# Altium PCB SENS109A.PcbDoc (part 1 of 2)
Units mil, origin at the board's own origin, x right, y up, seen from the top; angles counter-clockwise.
Board outline 2760 x 2518.85 mil, 4 copper layers (Top Layer, Signal Layer 1, Signal Layer 2, Bottom Layer), stack 62.2 mil thick; 49 components, 21 nets, 113 pads, 294 vias.
Unrouted connection lines stored in the file: 4.
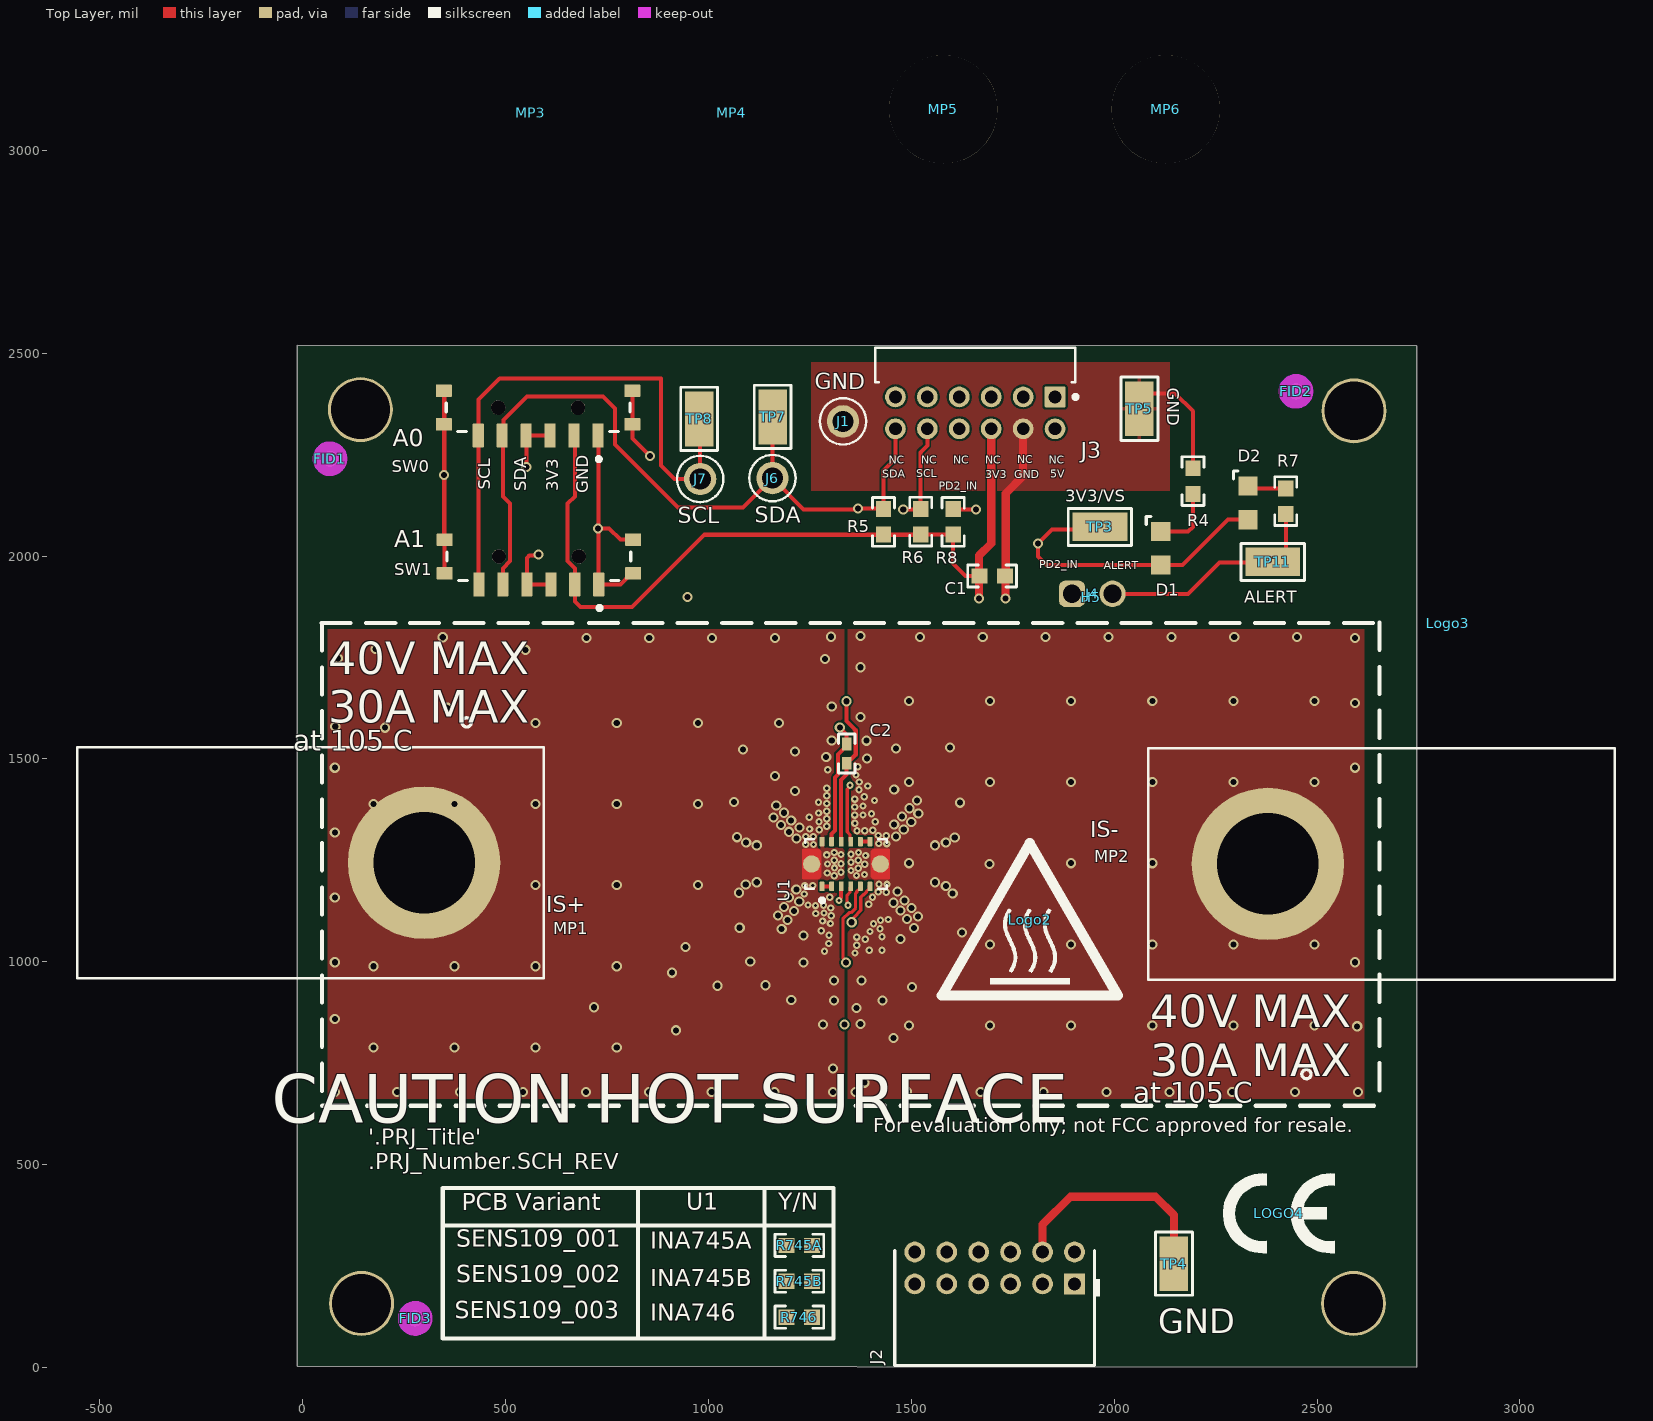
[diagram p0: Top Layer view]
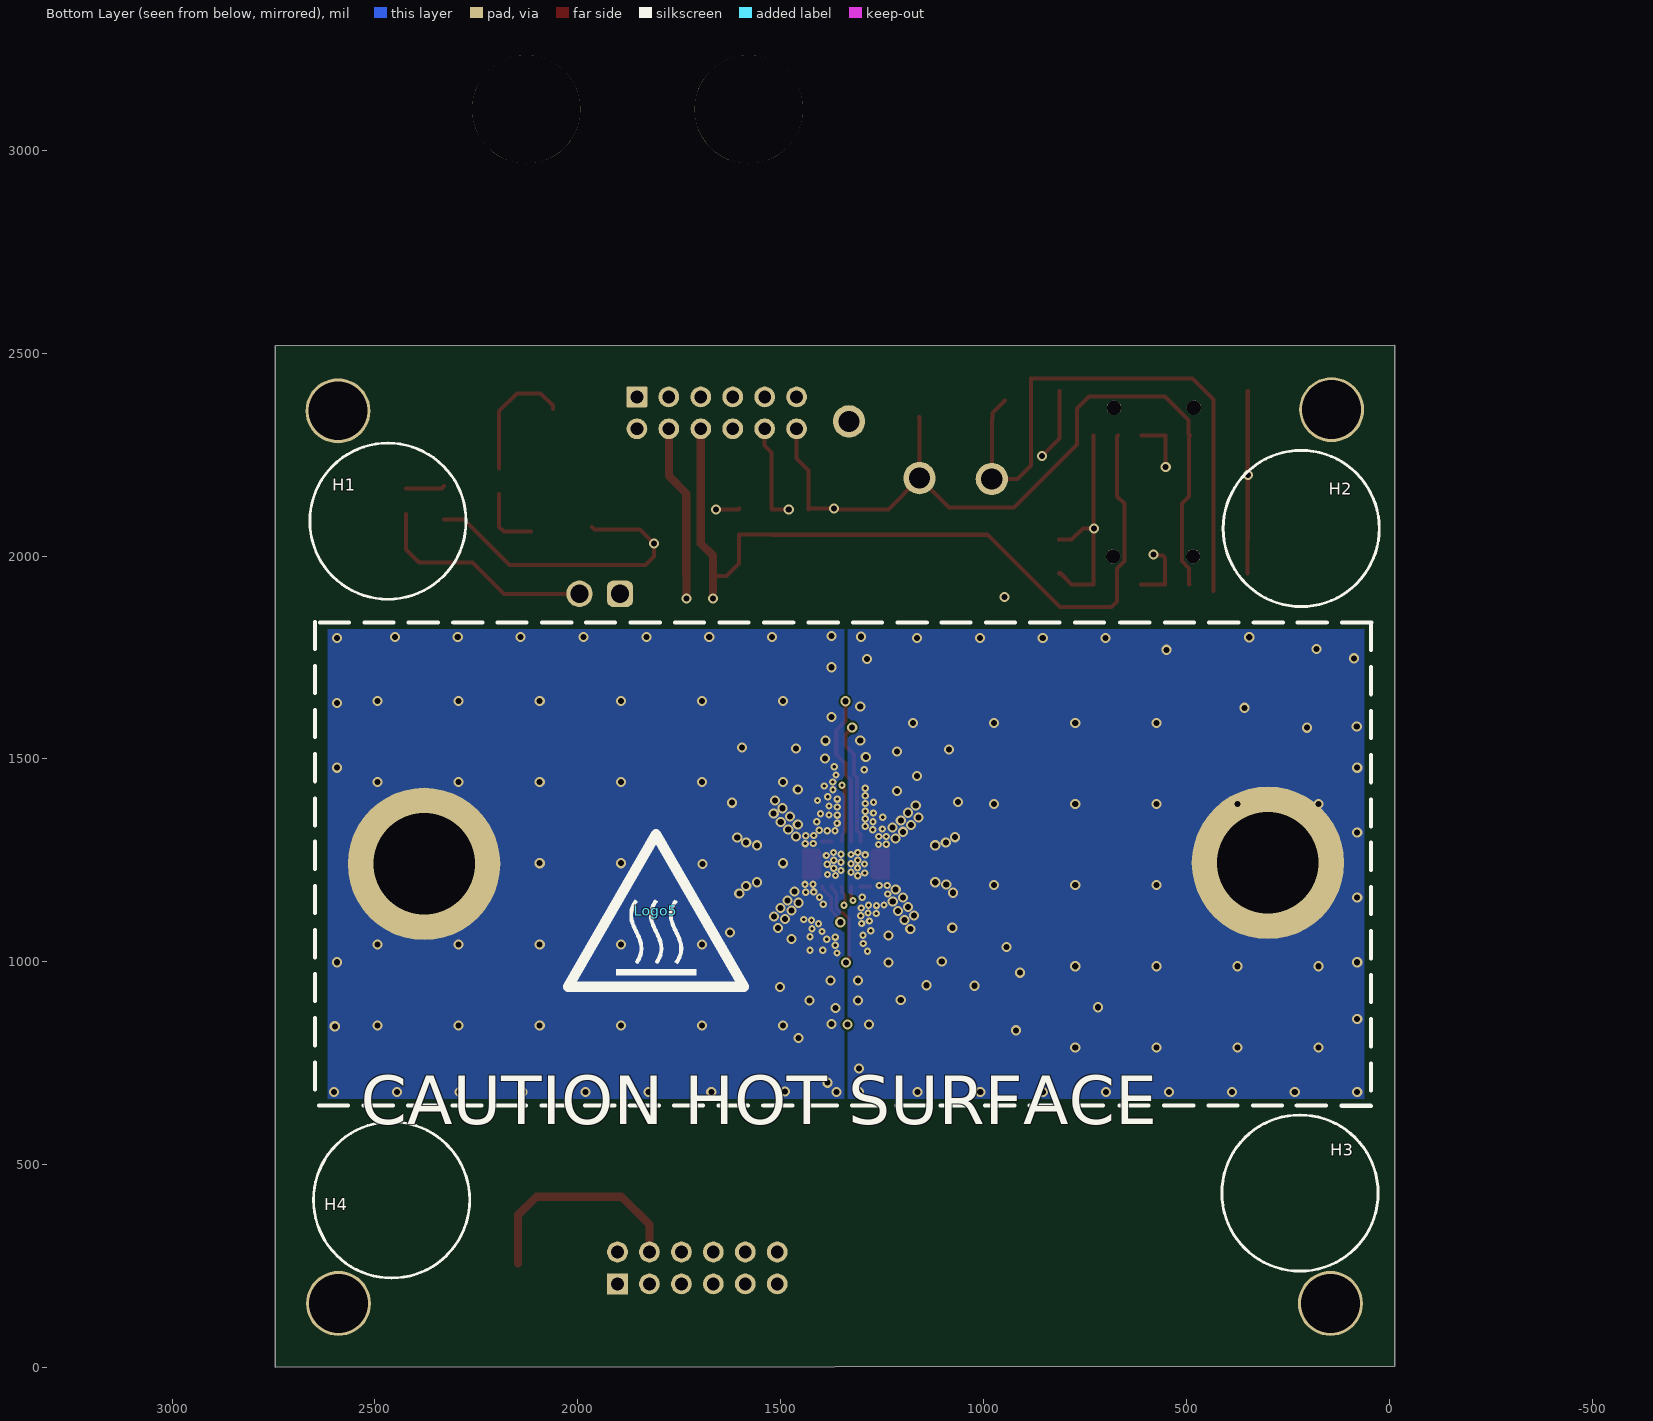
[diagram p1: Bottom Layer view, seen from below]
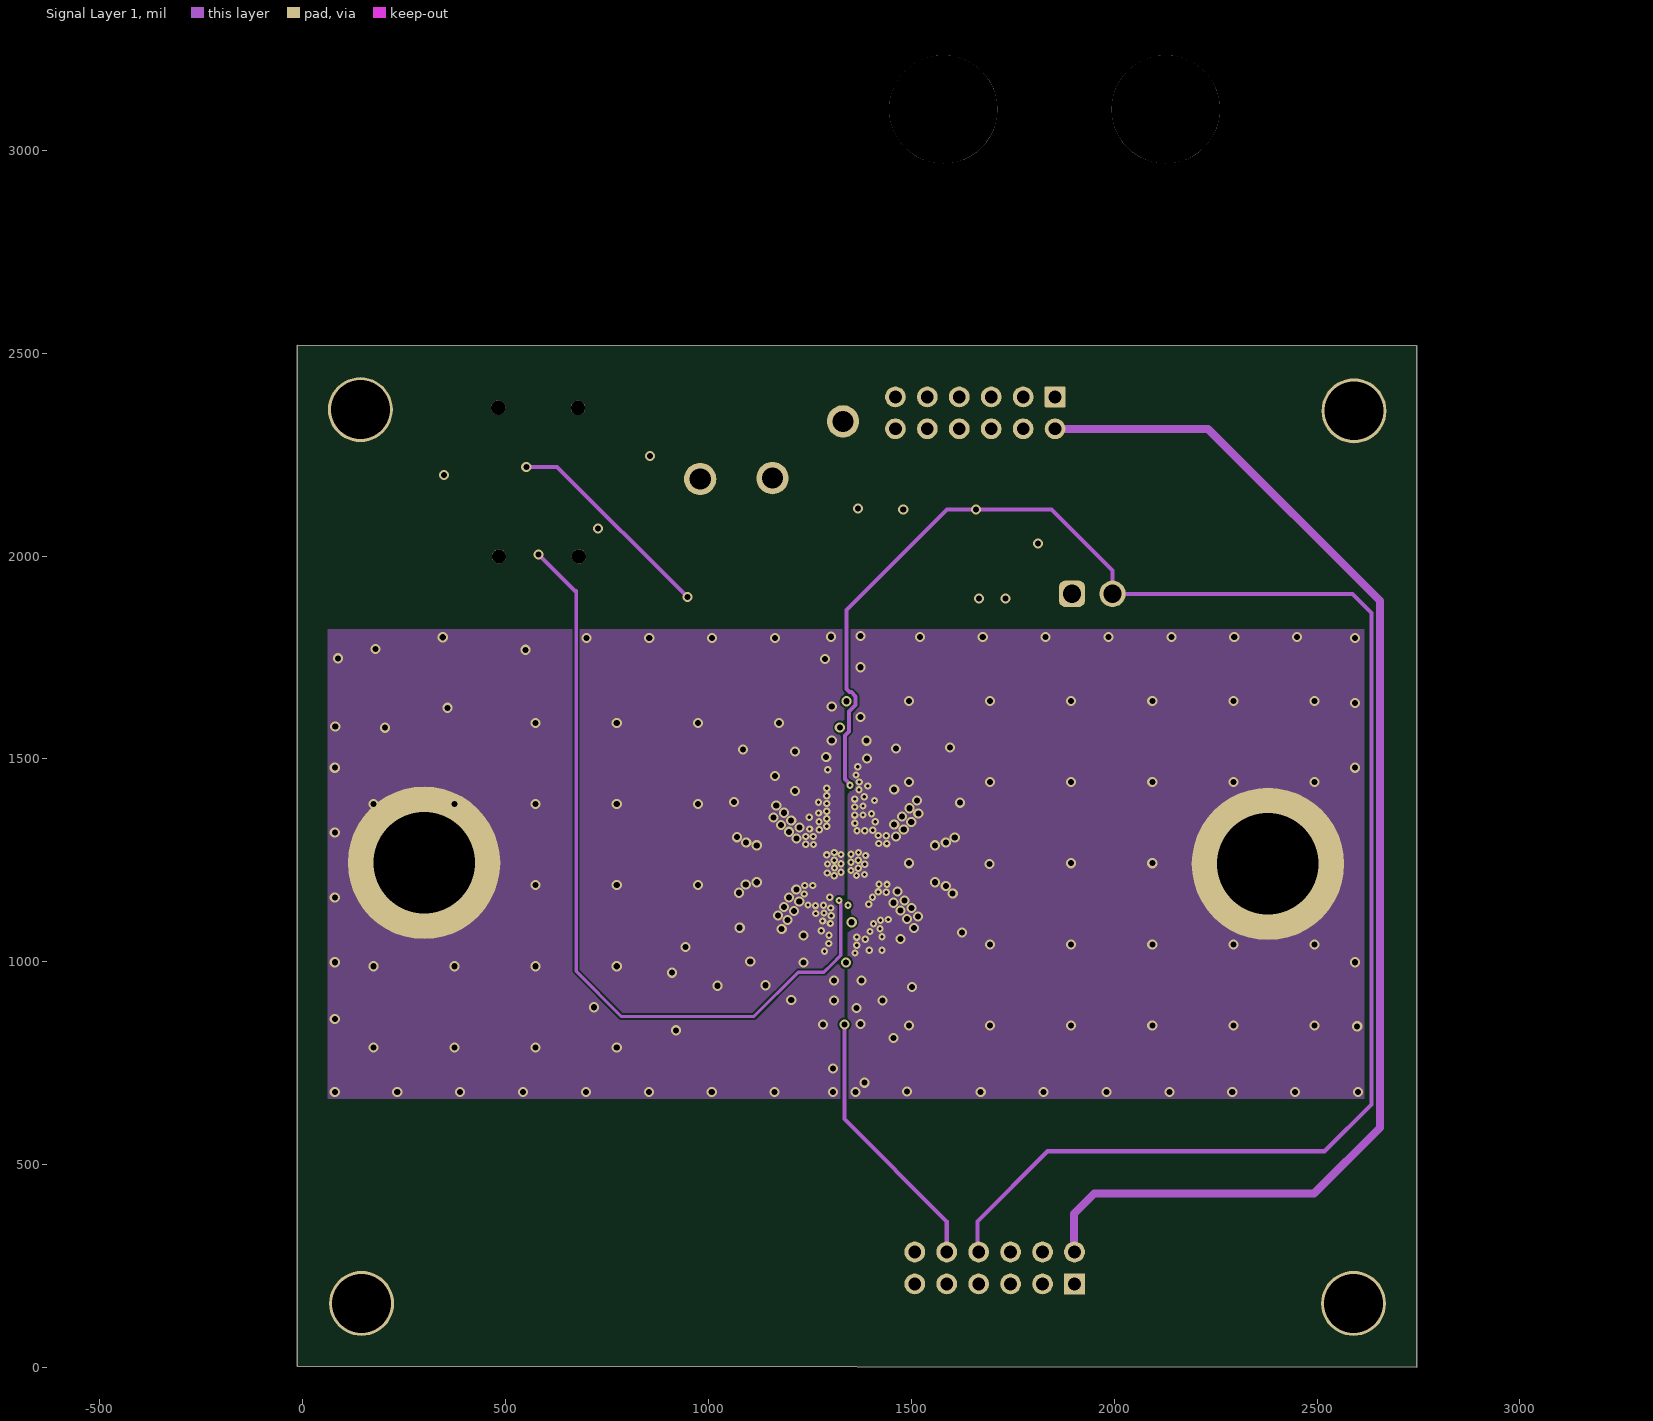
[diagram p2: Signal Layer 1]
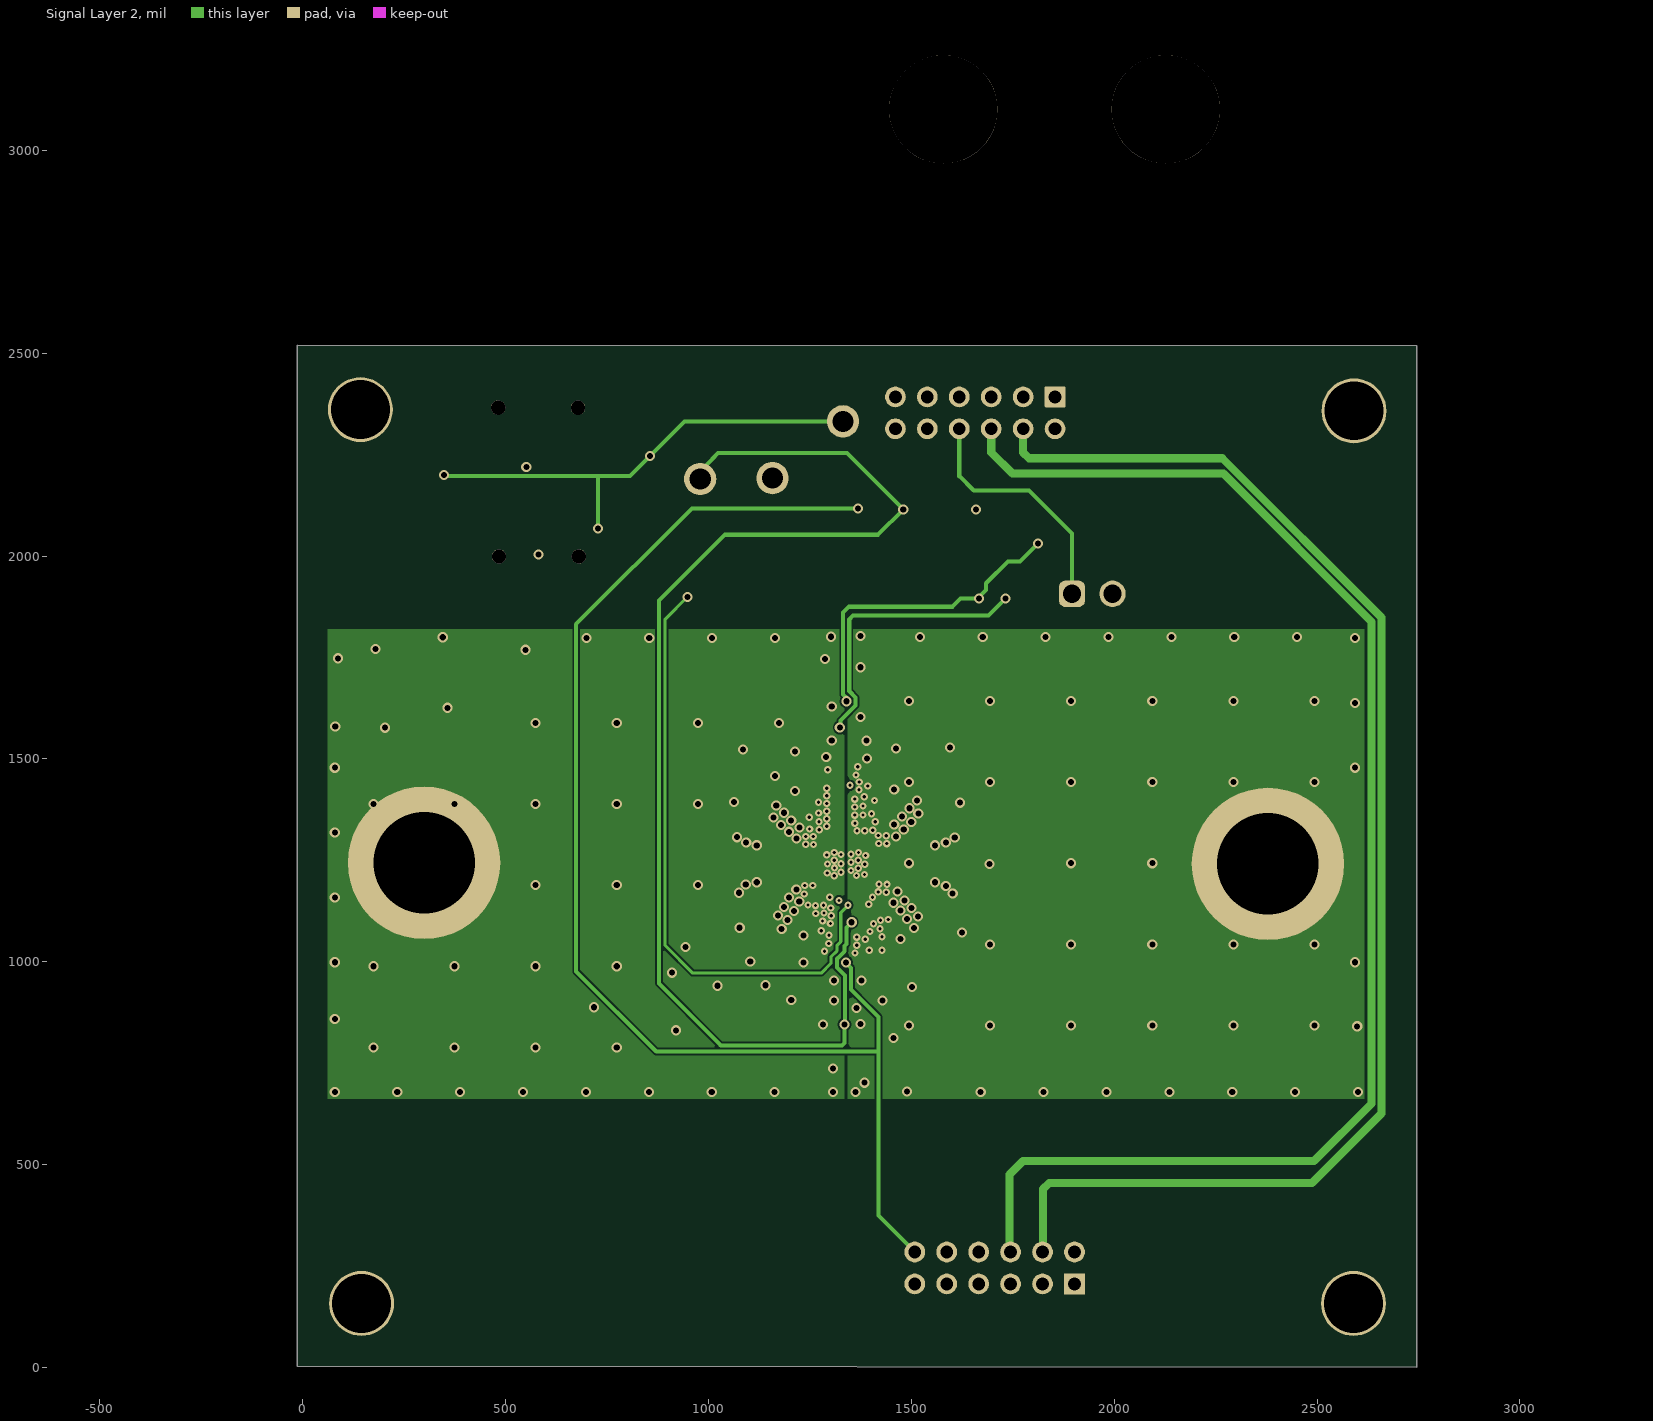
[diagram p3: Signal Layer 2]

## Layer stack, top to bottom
Top Solder: solder mask 0.4, Solder Resist, Dk 3.5
Top Layer: signal copper 2.8
Dielectric1: dielectric 17, FR-4, Dk 4.2
Signal Layer 1: signal copper 2.8
Dielectric 2: core 17, FR-4, Dk 4.2
Signal Layer 2: signal copper 2.8
Dielectric 3: dielectric 17, FR-4, Dk 4.2
Bottom Layer: signal copper 2.8
Bottom Solder: solder mask 0.4, Solder Resist, Dk 3.5

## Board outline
-14,3 -14,2520 2746,2518.15 2746,1.15

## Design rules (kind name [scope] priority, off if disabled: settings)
AcuteAngle [All] p1: minimum=4.50000000000000E+0001 checktracksonly=FALSE
AssemblyTestPointUsage [All] p1: valid=2
BoardOutlineClearance BoardOutlineClearance_MountingHoles [OnCopper and InComponentClass('Mounting Holes')] p1: gap=14 ignorepadtopadclearanceinfootprint=FALSE
BoardOutlineClearance BoardOutlineClearance_Poly [OnCopper and IsPoly] p2: gap=25 ignorepadtopadclearanceinfootprint=FALSE
BoardOutlineClearance [OnCopper and Not InComponentClass('Logo') and not InComponentClass('FiducialMark') and not InRegion(1000,500,4000,800) and not InPoly] p3: gap=75 ignorepadtopadclearanceinfootprint=FALSE
Clearance Clearance_1 [All] p1: gap=5 ignorepadtopadclearanceinfootprint=TRUE
Clearance Clearance_Keepouts [((IsTrack Or IsArc) And Not InPoly) And IsFree and IsKeepOut vs ((IsTrack Or IsArc) And Not InPoly) And IsFree and IsKeepOut] p2: gap=0 ignorepadtopadclearanceinfootprint=FALSE
Clearance Clearance_FiducialMark [IsKeepOut and InComponentClass('FiducialMark') vs IsPad and InComponentClass('FiducialMark')] p3: gap=0 ignorepadtopadclearanceinfootprint=FALSE
Clearance Clearance_IS+ [InNet('IS+') vs (InNet('+3V3') OR InNet('+5V') OR InNet('A0') OR InNet('A1') OR InNet('GND') OR InNet('NetD1_2') OR InNet('NetD2_2') OR InNet('PD2') OR InNet('PN4') OR InNet('PN5') OR InNet('PP0'))] p4: gap=5.12 ignorepadtopadclearanceinfootprint=TRUE
Clearance Clearance_IS- [InNet('IS-') vs (InNet('+3V3') OR InNet('+5V') OR InNet('A0') OR InNet('A1') OR InNet('GND') OR InNet('NetD1_2') OR InNet('NetD2_2') OR InNet('PD2') OR InNet('PN4') OR InNet('PN5') OR InNet('PP0'))] p5: gap=5.12 ignorepadtopadclearanceinfootprint=TRUE
ComponentClearance ComponentClearance_MountingHoles_FiducialMarks [InComponentClass('Mounting Holes') vs InComponentClass('FiducialMark')] p1: gap=50 collisioncheckmode=3 verticalgap=10 showdistances=FALSE
ComponentClearance ComponentClearance_Shunt [InComponentClass('Header') vs InComponentClass('Shunt')] p2: gap=0 collisioncheckmode=3 verticalgap=0 showdistances=FALSE
ComponentClearance ComponentClearance_Logo [InComponentClass('Logo')] p3: gap=20 collisioncheckmode=3 verticalgap=10 showdistances=FALSE
ComponentClearance ComponentClearance_ScrewToNut [(HasFootprint('NY PMS 440 0025 PH')) vs (HasFootprint('Keystone_1902C'))] p4: gap=5 collisioncheckmode=3 verticalgap=10 showdistances=FALSE
ComponentClearance ComponentClearance_MountingHoles [InComponentClass('Mounting Holes')] p5: gap=250 collisioncheckmode=3 verticalgap=100000 showdistances=FALSE
ComponentClearance ComponentClearance_SmallPassives [HasFootprint('0201*') or HasFootprint('0402*') or HasFootprint('0508') or HasFootprint('0603*') or HasFootprint('0612') or HasFootprint('0805*') or HasFootprint('0815*') or HasFootprint('0830*') or HasFootprint('1206*') or HasFootprint('1210*') or HasFootprint('1808*') or HasFootprint('1812*') or HasFootprint('1825*') or HasFootprint('2010*') or HasFootprint('2220*') or HasFootprint('2225*') or HasFootprint('2512*') or HasFootprint('2728*') or HasFootprint('3518*') vs HasFootprint('0201*') or HasFootprint('0402*') or HasFootprint('0508') or HasFootprint('0603*') or HasFootprint('0612') or HasFootprint('0805*') or HasFootprint('0815*') or HasFootprint('0830*') or HasFootprint('1206*') or HasFootprint('1210*') or HasFootprint('1808*') or HasFootprint('1812*') or HasFootprint('1825*') or HasFootprint('2010*') or HasFootprint('2220*') or HasFootprint('2225*') or HasFootprint('2512*') or HasFootprint('2728*') or HasFootprint('3518*')] p6: gap=14.96 collisioncheckmode=3 verticalgap=10 showdistances=FALSE
ComponentClearance ComponentClearance_THtoSMT [IsThruComponent vs IsSMTComponent] p7: gap=40 collisioncheckmode=3 verticalgap=30 showdistances=FALSE
ComponentClearance ComponentClearance_THtoTH [IsThruComponent vs IsThruComponent] p8: gap=30 collisioncheckmode=3 verticalgap=30 showdistances=FALSE
ComponentClearance [All] p9: gap=30 collisioncheckmode=3 verticalgap=10 showdistances=FALSE
DiffPairsRouting [All] p1: maxlimit=100 minlimit=10 mostfreqgap=10 toplayer_minwidth=15 toplayer_maxwidth=15 toplayer_prefwidth=15 midlayer1_minwidth=15 midlayer1_maxwidth=15 midlayer1_prefwidth=15 midlayer2_minwidth=15 midlayer2_maxwidth=15 midlayer2_prefwidth=15 bottomlayer_minwidth=15 bottomlayer_maxwidth=15 bottomlayer_prefwidth=15 maxuncoupledlength=1000
FabricationTestPointUsage TestPointUsage [All] p1: valid=2 allowmultiple=FALSE
FabricationTestpoint Testpoint [All] p1: side=3 testpointundercomponent=TRUE minsize=40 maxsize=100 preferedsize=60 minholesize=0 maxholesize=40 preferedholesize=32 testpointgrid=1 allowsidetop=TRUE allowsidebottom=TRUE usegrid=TRUE gridtolerance=0.01
FanoutControl Fanout_LCC [IsLCC] p1: bgadir=Out bgaviamode=Centered fanoutstyle=Auto fanoutdirection=Alternating viagrid=1 // Fanout_LCC (Default Rule)
FanoutControl Fanout_BGA [IsBGA] p2: bgadir=Out bgaviamode=Centered fanoutstyle=Auto fanoutdirection=Alternating viagrid=1 // Fanout_BGA (Default Rule)
FanoutControl Fanout_Default [All] p4: bgadir=Out bgaviamode=Centered fanoutstyle=Auto fanoutdirection=Alternating viagrid=1 // Fanout_Default (Default Rule)
FanoutControl Fanout_Small [(CompPinCount < 5)] p5: bgadir=Out bgaviamode=Centered fanoutstyle=Auto fanoutdirection=OutThenIn viagrid=1 // Fanout_Small (Default Rule)
HoleSize [All] p1: absolutevalues=TRUE maxlimit=251 minlimit=8 maxpercent=80.000 minpercent=20.000
HoleToHoleClearance [All] p1: gap=8 allowstackedmicrovias=TRUE
MinimumAnnularRing MinimumAnnularRing_ThermalPadVias [IsVia and InAnyComponent] p1: minimumring=5
MinimumAnnularRing [All] p2: minimumring=5
MinimumSolderMaskSliver MinimumSolderMaskSliver_Logo [InComponentClass('Logo') vs InComponentClass('Logo')] p1: minsoldermaskwidth=0.7
MinimumSolderMaskSliver [All] p2: minsoldermaskwidth=4
PlaneConnect [All] p1: planeconnectstyle=Direct reliefexpansion=10 reliefentries=4 reliefconductorwidth=10 reliefairgap=10
PolygonConnect PolygonConnect_Trace [InNet('NetJ1_5') OR InNet('NetJ1_3')] p1: connectstyle=Direct reliefconductorwidth=10 reliefentries=4 polygonreliefangle="90 Angle" airgapwidth=10
PolygonConnect [All] p2: connectstyle=Direct reliefconductorwidth=10 reliefentries=4 polygonreliefangle="90 Angle" airgapwidth=10
RoutingVias [All] p1: holewidth=10 width=20 viastyle="Through Hole" minholewidth=4 minwidth=15 maxholewidth=40 maxwidth=65
SilkToBoardRegionClearance [Not ((IsComment or IsDesignator) And (Hide <> 'False')) and not InRegion(1000,500,4000,800)] p1:
SilkToSilkClearance SilkToSilkClearance_Pb-FreeLogo [(HasFootprint('Pb-Free_Overlay_Medium') OR HasFootprint('Pb-Free_Overlay_Small')) vs (HasFootprint('Pb-Free_Overlay_Medium') OR HasFootprint('Pb-Free_Overlay_Small'))] p1: silktosilkclearance=0
SilkToSilkClearance [All] p2: silktosilkclearance=3.94
SilkToSolderMaskClearance SilkToComponentPadClearance [(IsPad or IsFill or IsRegion) and InAnycomponent] p1: minsilkscreentomaskgap=5 clearancetoexposedcopper=TRUE
SilkToSolderMaskClearance "Silk to Solder Mask Opening" [All] p2: minsilkscreentomaskgap=3.94 clearancetoexposedcopper=FALSE
SolderMaskExpansion [All] p1: expansion=1.97 istentingtop=FALSE
UnRoutedNet [All] p1: checkbadconnections=TRUE
Width [All] p1: maxlimit=100 minlimit=5 preferedwidth=10 checkconnectedcopper=TRUE
13 further rules are at their usual default settings.

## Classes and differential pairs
component class Shunt: H5
component class Header: J4
component class SENS109A: "ALERT BUS" C1 C2 C3 D1 D2 J1 J2 J3 J4 J6 J7 MP1 MP2 q R4 R5 R6 R7 R8 R745A R745B R746 SW0 SW1 SW2 SW? TP3 TP4 TP5 TP7 TP8 TP11 U1
component class SENS109A_HW: FID1 FID2 FID3 H1 H2 H3 H4 H5 Logo2 Logo3 LOGO4 Logo5 MP3 MP4 MP5 MP6 ZZ1 ZZ2 ZZ3 ZZ4
component class FiducialMark: FID1 FID2 FID3
component class AssemblyNote: ZZ1 ZZ2 ZZ3 ZZ4

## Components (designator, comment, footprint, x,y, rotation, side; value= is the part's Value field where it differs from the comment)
C1 "C1608X6S1H105K080AC" 0603 1699,1951.12 r0 top value=1uF
C2 "GRM155R71H104ME14D" 0402 1340.64,1513.12 r90 top value=0.1uF
D1 "POWER" VAOL-0805_White 2115,2019 r90 top
D2 "ALERT" VAOL-0805_White 2330,2131 r90 top
FID1 "Fiducial" Fiducial10-20 67,2240 r0 top
FID2 "Fiducial" Fiducial10-20 2448,2406 r0 top
FID3 "Fiducial" Fiducial10-20 277,121 r0 top
H1 "SJ61A2" Bumpon_SJ61A2 2468,2086.12 r180 bottom
H2 "SJ61A2" Bumpon_SJ61A2 217,2068 r180 bottom
H3 "SJ61A2" Bumpon_SJ61A2 220,430 r180 bottom
H4 "SJ61A2" Bumpon_SJ61A2 2459,413 r180 bottom
H5 "60900213421" Wurth_60900213421 1944,1898 r0 top
J1 "GND" FP-3-331272-8_PIN_RCPT-MFG 1331.66,2332.12 r0 top
J2 "NPPN062FJFN-RC" Sullins_NPxN062FJFN 1705.37,245.37 r180 top
J3 "NRPN062PARN-RC" FP-NRPN062PARN-RC_HDR12-MFG 1657.55,2471.12 r180 top
J4 "ALERT BUS" WURTH_61300211121 1946,1907 r0 top
J6 "SDA" FP-3-331272-8_PIN_RCPT-MFG 1157.66,2192.12 r0 top
J7 "SCL" FP-3-331272-8_PIN_RCPT-MFG 979.66,2190.12 r0 top
Logo2 "CAUTION HOT SURFACE" IEC_HotSurface_Medium 1792,1104 r0 top
Logo3 "FCC disclaimer" FCC_disclaimer 2822,1834.12 r90 top
LOGO4 "CE Mark" CE_Mark_5mm 2406,380 r0 top
Logo5 "CAUTION HOT SURFACE" IEC_HotSurface_Medium 1807.5,1126 r180 bottom
MP1 "LAMA6-14-QY" FP-LAMA6-14-QY_TERMINAL_CONN-MFG 19,1244 r0 top
MP2 "LAMA6-14-QY" FP-LAMA6-14-QY_TERMINAL_CONN-MFG 2659,1241.12 r180 top
MP3 "95462A029" FP-95462A029_NUT_1-4-20-MFG 562,3093.12 r0 top
MP4 "95462A029" FP-95462A029_NUT_1-4-20-MFG 1058,3093.12 r0 top
MP5 "92196A535" FP-90283A537-MFG 1579,3101.12 r0 top
MP6 "92196A535" FP-90283A537-MFG 2127,3101.12 r0 top
R4 "CRCW060310K0JNEA" 0603 2194,2185 r270 top value=10k
R5 "CRCW06034K70JNEA" 0603 1431.17,2084.12 r270 top value=4.7k
R6 "CRCW06034K70JNEA" 0603 1523.17,2085.12 r270 top value=4.7k
R7 "CRCW060310K0JNEA" 0603 2423,2135.5 r90 top value=10k
R8 "CRCW06034K70JNEA" 0603 1603.17,2084.12 r270 top value=4.7k
R745A "INA745A" 0603 1224,301 r0 top value=4.7k
R745B "INA745B" 0603 1224,212.5 r0 top value=4.7k
R746 "INA746" 0603 1224,124 r0 top value=4.7k
SW0 "CUS-14TB" FP-CUS-14TB_SMT_SW_11MM3_4MM1-MFG 580,2366 r180 top
SW1 "CUS-14TB" FP-CUS-14TB_SMT_SW_11MM3_4MM1-MFG 582,1999 r180 top
TP3 "3V3/VS" Testpoint_Keystone_Miniature 1965,2072 r0 top
TP4 "GND" Testpoint_Keystone_Miniature 2147,256 r90 top
TP5 "GND" Testpoint_Keystone_Miniature 2061.66,2363.12 r90 top
TP7 "SDA" Testpoint_Keystone_Miniature 1158.66,2343.12 r270 top
TP8 "SCL" Testpoint_Keystone_Miniature 977.66,2338.12 r270 top
TP11 "ALERT" Testpoint_Keystone_Miniature 2391,1986 r0 top
U1 "INA745BIRELR" REL0014B-MFG 1339,1241.12 r90 top
ZZ1 "This Assembly Note is for PCB labels only" AssemblyNoteLabel -129,3806.12 r0 top
ZZ2 "These assemblies are ESD sensitive, ESD precautions shall be observed." AssemblyNote -129,3697.24 r0 top
ZZ3 "These assemblies must be clean and free from flux and all contaminants. Use of no clean flux is not acceptable." AssemblyNote -129,3608.68 r0 top
ZZ4 "These assemblies must comply with workmanship standards IPC-A-610 Class 2, unless otherwise specified." AssemblyNote -129,3520.12 r0 top

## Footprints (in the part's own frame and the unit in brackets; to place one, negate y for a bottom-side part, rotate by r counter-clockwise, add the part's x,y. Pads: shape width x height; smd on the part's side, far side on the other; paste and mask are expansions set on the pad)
0402 [mm] "0402 from SM-752 data"
  rect 0.8x0.6 smd: 1(-0.6,0) 2(0.6,0)
  silkscreen extent -1.22,-0.52 1.22,0.52, body extent -0.55,-0.3 0.55,0.3, height 0.6
0603 [mm] "0603 from SM-752 data"
  rect 1x0.95 smd: 1(-0.8,0) 2(0.8,0)
  silkscreen extent -1.52,-0.69 1.52,0.69, body extent -0.87,-0.47 0.87,0.47, height 1
AssemblyNote [mil] "Assembly Note"
AssemblyNoteLabel [mil] "Assembly Note for PCB Labels"
Bumpon_SJ61A2 [mil] "3M Hemispherical Bumpon transparent"
  round 1 on Mech4: 0(0,0)
  silkscreen extent -192,-192 192,192, body extent -193,-193 193,193, height 250
CE_Mark_5mm [mil] "Minimum text height for CE Mark"
  silkscreen extent -138,-98 138,98
FCC_disclaimer [mil]
Fiducial10-20 [mm]
  round 1 smd mask+0.5: 1(0,0)
  Top Layer keep-out circle w1.178: c0,0 r0.5
FP-3-331272-8_PIN_RCPT-MFG [mm]
  round 2.02 hole 1.32 paste-1000 mask+0: 1(0,0)
  silkscreen extent -1.45,-1.45 1.45,1.45, body extent -1.11,-1.11 1.11,1.11, height 0.25
FP-90283A537-MFG [mil]
  round 267 hole 267 unplated paste-39370.1 mask+0: ""(0,0)
  body extent -246,-246 246,246, height 143
FP-95462A029_NUT_1-4-20-MFG [mil]
  body extent -223,-257 223,257, height 10
FP-CUS-14TB_SMT_SW_11MM3_4MM1-MFG [mm]
  rrect14% 0.7x1.5 smd paste+0 mask+0: 1(-3.75,1.75) 2(-2.25,1.75) 3(-0.75,1.75) 4(0.75,1.75) 5(2.25,1.75) 6(3.75,1.75)
  rrect13% 1x0.8 smd paste+0 mask+0: 7(-5.9,1.05) 8(5.9,1.05) 9(-5.9,-1.05) 10(5.9,-1.05)
  round 0.9 hole 0.9 unplated paste-1000 mask+0: ""(-2.5,0) ""(2.5,0)
  silkscreen extent -5.75,-0.28 5.75,3.35, body extent -6.5,-3.1 6.5,2.6, height 0.25
FP-LAMA6-14-QY_TERMINAL_CONN-MFG [mm]
  round 9.55 hole 6.35 paste-1000 mask+0: 1(7.112,0)
  silkscreen extent -14.6,-7.24 14.6,7.24, body extent -14.32,-6.96 14.32,6.96, height 0.25
FP-NRPN062PARN-RC_HDR12-MFG [mm]
  rrect8% 1.3x1.3 hole 0.8 paste-1000 mask+0: 1(-5,2)
  round 1.3 hole 0.8 paste-1000 mask+0: 2(-5,4) 3(-3,2) 4(-3,4) 5(-1,2) 6(-1,4) 7(1,2) 8(1,4) 9(3,2) 10(3,4) 11(5,2) 12(5,4)
  silkscreen extent -6.4,-1.07 6.25,2.12, body extent -6.35,-5.02 6.35,4.75, height 0.25
IEC_HotSurface_Medium [mil]
  silkscreen extent -217,-188 217,188
REL0014B-MFG [mm]
  rrect33% 0.6x0.3 smd paste+0 mask+0: 1(-1.4,1.5) 2(-1.4,0.9) 3(-1.4,0.3) 4(-1.4,-0.3) 5(-1.4,-0.9) 6(-1.4,-1.5) 8(1.4,-1.5) 9(1.4,-0.9) 10(1.4,-0.3) 11(1.4,0.3) 12(1.4,0.9) 13(1.4,1.5)
  round 1.08 smd paste-1000 mask-1000: 7(0,-2.15) 14(0,2.15)
  Top Layer region: 0.7,-1.55 0.825,-1.583 0.917,-1.675 0.95,-1.8 0.95,-1.8 0.95,-2.65 0.937,-2.7 0.9,-2.737 0.85,-2.75 0.85,-2.75 -0.85,-2.75 -0.9,-2.737 -0.937,-2.7 -0.95,-2.65 -0.95,-2.65 -0.95,-1.8 -0.917,-1.675 -0.825,-1.583 -0.7,-1.55 -0.7,-1.55
  Top Layer region: -0.7,1.55 -0.825,1.583 -0.917,1.675 -0.95,1.8 -0.95,1.8 -0.95,2.65 -0.937,2.7 -0.9,2.737 -0.85,2.75 -0.85,2.75 0.85,2.75 0.9,2.737 0.937,2.7 0.95,2.65 0.95,2.65 0.95,1.8 0.917,1.675 0.825,1.583 0.7,1.55 0.7,1.55
  silkscreen extent -2.4,-2.55 1.55,2.55, body extent -1.8,-2.85 1.8,2.85, height 0.25
Sullins_NPxN062FJFN [mm] "Receptacle, 2mm, 6x2, R/A, TH"
  rect 1.3x1.3 hole 0.8: 1(-5,1)
  round 1.3 hole 0.8: 2(-5,-1) 3(-3,1) 4(-3,-1) 5(-1,1) 6(-1,-1) 7(1,1) 8(1,-1) 9(3,1) 10(3,-1) 11(5,1) 12(5,-1)
  silkscreen extent -6.6,-1.1 6.25,6.1, body extent -6.25,-1.1 6.25,6.1, height 4.85
Testpoint_Keystone_Miniature [mil] "Miniature SMT test point"
  rect 135x70 smd: 1(0,0)
  silkscreen extent -78,-46 78,45, body extent -52,-20 52,20, height 61
VAOL-0805_White [mm] "Visual Communications"
  rect 1.2x1.2 smd: 1(-1.05,0) 2(1.05,0)
  silkscreen extent 1.5,0.63 2,0.91, body extent -1.05,-0.67 1.05,0.67, height 1.1
Wurth_60900213421 [mil] "Shunt, 2.54mm, Black"
  round 1 on Mech3: 0(0,0)
  body extent -98,-48 98,48, height 338
WURTH_61300211121 [mm] "Header, 2.54mm, 2x1, TH"
  rrect50% 1.65x1.65 hole 1.15: 1(-1.27,0)
  round 1.65 hole 1.15: 2(1.27,0)
  body extent -2.54,-1.27 2.54,1.27, height 8.54

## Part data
C1: library part CMP-0007029-4, "CAP, CERM, 1 uF, 50 V, +/- 10%, X6S, 0603", Cap_Case=0603, Manufacturer=TDK, Supplier Part Number 1=445-7424-1-ND, TempCo=X6S, Tolerance_%=10%, Value1="0.005522 ohm", Value2=50V, ValueDisplayed=1uF
C2: library part CMP-0006675-2, "CAP, CERM, 0.1 uF, 50 V, +/- 20%, X7R, 0402", Cap_Case=0402, Manufacturer=MuRata, Supplier Part Number 1=490-10701-1-ND, TempCo=X7R, Tolerance_%=20%, Value1=Unknown, Value2=50V, ValueDisplayed=0.1uF
D1 D2: library part CMP-0002885-2, "LED, White, SMD", Color=White, Manufacturer="Visual Communications Company, LLC", PartNumber=VAOL-S8WR4, Value1=W, Value2=2.925V
FID1 FID2 FID3: library part CMP-0077181-1, "Fiducial mark.  There is nothing to buy or mount.", Manufacturer=N/A
H1 H2 H3 H4: library part CMP-0003622-1, "Bumpon, Hemisphere, 0.375 X 0.235, Black", Manufacturer=3M, Supplier Part Number 1=SJ5748-0-ND
H5: library part CMP-0003761-2, "Shunt, 2.54mm, Gold, Black", Manufacturer="Wurth Elektronik", Supplier Part Number 1=732-2678-ND
J1 J6 J7: library part CMP-0086763-1, "CONN PIN RCPT .018-.021 SOLDER", Current_A=5A, Manufacturer="TE Connectivity", PartNumber=3-331272-8
J2: library part CMP-0054670-1, "Receptacle, 2mm, 6x2, Gold, R/A, TH", Color=Black, Manufacturer="Sullins Connector Solutions", Supplier Part Number 1=S5753-06-ND
J3: library part CMP-0090321-1, Current_A=2A, Digikey Part Number=S5803-06-ND, Manufacturer="Sullins Connector Solutions", Operating Temperature Range="-40°C to +105°C", Voltage_V=150V
J4: library part CMP-0054794-2, "Header, 2.54 mm, 2x1, Gold, TH", Color=Black, Manufacturer="Wurth Elektronik", PartNumber=61300211121, Supplier Part Number 1=732-5315-ND
Logo2 Logo5: library part CMP-0074837-2, "IEC 61010-1 Hot Surface Warning", Manufacturer="Texas Instruments"
Logo3: library part CMP-0074847-1, "FCC_disclaimer"
LOGO4: library part CMP-0074844-1
MP1 MP2: library part CMP-0091352-2, "Terminal Connector Rectangular Lug, Grounding 6-14 AWG 1/4 Stud", Digikey Part Number=298-10102-ND, Manufacturer=Panduit, Mouser Part Number=644-LAMA6-14-QY, Operating Temperature Range=to
MP3 MP4: library part CMP-0088009-1, "Medium-Strength Steel Hex Nut", Manufacturer=McMASTER-CARR
MP5 MP6: library part CMP-0088011-2, Manufacturer=McMaster-CARR, PartNumber=90283A537
R4 R7: library part CMP-0025701-3, "RES, 10 k, 5%, 0.1 W, 0603", Manufacturer=Vishay-Dale, Power_W=100mW, Supplier Part Number 1=541-10KGCT-ND, TempCo="200 ppm/C", Tolerance_%=5%, Value2=0.1W, Value_Code=10k0, ValueDisplayed=10k
R5 R6 R8: library part CMP-0025817-3, "RES, 4.7 k, 5%, 0.1 W, 0603", Manufacturer=Vishay-Dale, Power_W=100mW, Supplier Part Number 1=541-4.7KGCT-ND, TempCo="200 ppm/C", Tolerance_%=5%, Value2=0.1W, Value_Code=4k70, ValueDisplayed=4.7k
R745A R745B R746: library part CMP-0025817-3, "RES, 4.7 k, 5%, 0.1 W, 0603", Manufacturer=Vishay-Dale, PartNumber=CRCW06034K70JNEA, Power_W=100mW, Supplier Part Number 1=541-4.7KGCT-ND, TempCo="200 ppm/C", Tolerance_%=5%, Value2=0.1W, Value_Code=4k70, ValueDisplayed=4.7k
SW0 SW1: library part CMP-0088487-2, "Slide Switch SP4T Surface Mount, Right Angle", Coil Resistance_ohm=70mΩ, Contact Current Rating=300mA, Digikey Part Number=563-1104-1-ND, Manufacturer="Nidec Copal Electronics", Operating Force=1.5/2/2/1.5/2/2N, Operating Temperature Range="-20°C to +70°C"
TP3 TP4 TP5 TP7 TP8 TP11: library part CMP-0055152-1, "Test Point, Miniature, SMT", Manufacturer=Keystone, PartNumber=5015, Supplier Part Number 1=36-5015TR-ND
U1: library part CMP-0096083-1, "40-V, Integrated Sense Element, 16-Bit, Precision Power/Energy/Charge Monitor With I 2C Interface", Manufacturer="Texas Instruments", Max Supply Voltage=5.5V, Min Supply Voltage=2.7V, Nominal Supply Current=640uA, Operating Temperature Range="to +165°C"
ZZ1: library part CMP-0003616-3
ZZ2: library part CMP-0077236-1
ZZ3: library part CMP-0077237-1
ZZ4: library part CMP-0077238-1

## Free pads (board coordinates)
  round 160 hole 145: 3(142,2361) 3(145,158) 3(2590,158) 3(2591,2358)

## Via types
v1: diameter 25, hole 15, Top Layer to Bottom Layer, tented both sides, 193 vias
v2: diameter 18, hole 8, Top Layer to Bottom Layer, tented both sides, 97 vias
v3: diameter 25, hole 15, Top Layer to Bottom Layer, 4 vias

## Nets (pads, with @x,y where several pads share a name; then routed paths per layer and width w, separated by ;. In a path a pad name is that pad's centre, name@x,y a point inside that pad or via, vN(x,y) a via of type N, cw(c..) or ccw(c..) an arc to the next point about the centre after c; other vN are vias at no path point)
+3V3: C1.1 C2.1 D1.1 D2.1 J2.6 J3.6 R5.2 R6.2 R8.2 SW0.2 SW1.2 TP3.1 U1.11 | length 7461.4
  Top Layer w10: SW0.2@668.58,2297.1 670.58,2295.1 670.58,2146.98 652.71,2129.11 652.71,1987.52 670.58,1969.65 SW1.2@670.58,1930.1 670.58,1888.42 685,1874 812,1874 990.63,2052.63 R5.2@1431.17,2052.63 1522.17,2052.63 R6.2@1523.17,2053.63 1602.17,2053.63 R8.2@1603.17,2052.63 1603.17,1982.28 1602.51,1981.62 1633,1951.12 1667,1951.12 C1.1@1667.5,1951.12 ; U1.11@1327.19,1296.24 1327.19,1448.51 1340.64,1461.96 C2.1@1340.64,1489.5 1342.17,1489.5 1363,1510.33 1363,1570.72 1355.5,1578.22 1355.5,1578.45 1340,1593.95 v3(1340,1642.12) ; TP3.1@1965,2072 1959,2066 1847.03,2066 v1(1812,2030.97) 1812,1999 1833.34,1977.66 D1.1@2115,1977.66 2168.66,1977.66 2280.66,2089.66 D2.1@2330,2089.66
  Top Layer w20: v1(1667,1895.12) 1667,1951.12 1667,2001.12 1696.92,2031.04 J3.6@1696.92,2313.64
  Signal Layer 2 w10: v3(1340,1642.12) 1337.13,1644.99 1337.13,1654.19 1332,1659.32 1332,1861.27 1345.86,1875.12 1601.35,1875.12 1621.35,1895.12 v1(1667,1895.12) 1667,1899.18 1684.01,1916.19 1684.01,1933.01 1738.12,1987.12 1768.15,1987.12 1776.66,1995.63 v1(1812,2030.97)
  Signal Layer 2 w20: J3.6@1696.92,2313.64 1696.92,2255.65 1749.45,2203.12 2269,2203.12 2634,1838.12 2634,650.12 2492.88,509 1775,509 1742,476 1742,287.48 J2.6@1744.74,284.74
+5V: J2.2 J3.2 | length 3211.7
  Signal Layer 1 w20: J3.2@1854.4,2313.64 2231.36,2313.64 2655,1890 2655,591 2493,429 1951,429 1901,379 1901,285.96 J2.2@1902.22,284.74
A0: SW0.3 SW0.4 U1.4 | length 2206.7
  Top Layer w8: v2(1344.09,1139.37) 1344.09,1142.07 1341.19,1144.97 1341.19,1163.2 1348.91,1170.91 1348.91,1183.03 U1.4@1350.88,1185.01
  Top Layer w10: v1(551,2220) 551.24,2220.24 551.24,2296.87 551.47,2297.1 SW0.3@610.53,2297.1
  Signal Layer 1 w10: v1(551,2220) 627.12,2220 v1(948,1899.12)
  Signal Layer 2 w8: v1(948,1899.12) 893,1844.12 893,1040.12 961,972.12 1262.65,972.12 1262.77,972.24 1278.12,972.24 1302,996.12 1302,1012.74 1316.91,1027.65 1316.91,1040.63 1326.09,1049.81 1326.09,1121.37 v2(1344.09,1139.37)
A1: SW1.3 SW1.4 U1.3 | length 2150.5
  Top Layer w10: v1(581,2004) 578.13,2001.13 558.33,2001.13 552.47,1995.27 SW1.4@552.47,1930.1 SW1.3@611.53,1930.1 ; v2(1321.99,1151.29) 1321.99,1153.45 1327.19,1158.66 U1.3@1327.19,1186
  Signal Layer 1 w8: 674,1914.12 674,976.44 785.32,865.12 1112.12,865.12 1221.32,974.32 1284.63,974.32 1303.63,993.32 1303.8,993.32 1326.09,1015.62 v2@1326.09,1144.48
  Signal Layer 1 w10: v1(581,2004) 670.88,1914.12 674,1914.12
ALERT: J2.8 J4.2 R7.1 R8.1 TP11.1 U1.10 | length 5138
  Top Layer w8: v2@1349,1432.8 1349,1432.26 1342.19,1425.45 1342.19,1320.01 1348.91,1313.3 1348.91,1298.15 U1.10@1350.81,1296.24
  Top Layer w10: v2@1349,1432.8 v2(1349,1434.96) ; R8.1@1602.17,2116.62 R8.1@1603.17,2115.62 1604.05,2114.74 v1(1659.66,2114.74) ; J4.2@1996,1907 2182.34,1907 2259.34,1984 2389,1984 TP11.1@2391,1986 2393,1986 2423,2016 R7.1@2423,2104
  Signal Layer 1 w10: v2(1349,1434.96) 1349,1437.13 1336.18,1449.94 1336.18,1558.01 1346.21,1568.04 1346.21,1616.51 1362.5,1632.8 1362.5,1654.23 1352.11,1664.62 1347.91,1664.62 1340,1672.53 1340,1867.12 1587.62,2114.74 v1(1659.66,2114.74) 1845.26,2114.74 1996,1964 J4.2@1996,1907 2587.12,1907 2634,1860.12 2634,648.12 2518.88,533 1836,533 1663,360 1663,287.74 J2.8@1666,284.74
GND: C1.2 C2.2 J1.1 J2.4 J3.4 R4.1 SW0.1 SW0.7 SW0.8 SW0.9 SW0.10 SW1.1 SW1.7 SW1.8 SW1.9 SW1.10 TP4.1 TP5.1 U1.12 | length 8068.4
  Top Layer w10: SW0.8@347.72,2324.66 348.72,2323.66 348.72,2041.34 SW1.10@349.72,2040.34 SW1.8@349.72,1957.66 ; SW0.8@348.72,2324.66 SW0.10@348.72,2407.34 ; SW1.1@728.64,1930.1 728.64,2067.36 v1(728,2068) v1@728.64,2068 ; SW0.1@728.64,2297.1 v1@728.64,2068 ; SW1.1@729.64,1930.1 782.79,1930.1 810.35,1957.66 SW1.7@814.28,1957.66 ; SW0.9@813.28,2407.34 813.28,2289.72 v1(856,2247) v1@851.94,2247 ; SW1.9@814.28,2040.34 782.66,2040.34 755,2068 v1@728.64,2068 ; U1.12@1303.57,1296.24 1303.57,1315.3 1312.19,1323.92 1312.19,1454.72 1318.83,1461.36 1318.83,1511 1333.83,1526 1340.64,1532.81 1340.64,1560.42 v3(1323.71,1577.36) ; TP5.1@2061.66,2363.12 2061.66,2371 2091.66,2401 2150,2401 2194,2357 R4.1@2194,2216.5
  Top Layer w20: v1(1732,1895.12) 1732,1949.62 1732.66,1950.28 1732.66,2154.66 1775.66,2197.66 J3.4@1775.66,2313.64 ; J2.4@1823.48,284.74 1823.48,352.48 1892,421 2102,421 2147,376 TP4.1@2147,256
  Signal Layer 2 w10: v1(348,2200) 350.5,2197.5 728.64,2197.5 ; v1(728,2068) 728,2196.86 728.64,2197.5 ; v3(1323.71,1577.36) 1325.38,1579.03 1325.38,1594.58 1362.5,1631.7 1362.5,1651.44 1347,1666.94 1347,1844.12 1356,1853.12 1690,1853.12 v1(1732,1895.12) ; J1.1@1331.66,2332.12 941.12,2332.12 v1(856,2247) 806.5,2197.5 728.64,2197.5
  Signal Layer 2 w20: J3.4@1775.66,2313.64 1775.66,2255.65 1790.31,2241 2266.48,2241 2659,1848.48 2659,626 2488,455 1840,455 1825,440 1825,286.26 J2.4@1823.48,284.74
IS+: MP1.1 U1.13 U1.14
  other v1: 79,679.12 233,679.12 388,679.12 543,679.12 698,679.12 853,679.12 1008,679.12 1163,679.12 1307,679.12 1307,737 174,789 374,789 574,789 774,789 920,831.12 1282,845 79,859 718,888 1309.7,904.72 1204,906 1022,941 1140.23,942.18 1309.7,954.19 910,973.12 174,989 374,989 574,989 774,989 1234,998.12 79,998.84 1103,1001 943,1036.12 1234,1065 1180.53,1081.16 1077,1084 1194.93,1102.88 1171.02,1113.72 1210.8,1125.44 1186.51,1135.11 1223.87,1148.28 1198.9,1158.05 79,1158.69 1075,1170.12 1216.51,1178.38 574,1189 774,1189 974,1189 1092,1190.12 1119,1196.12 1119,1287.12 1093,1294.12 1217.26,1303.98 1070,1307.12 79,1318.55 1198.14,1320.38 1224.36,1330.58 1178.74,1336.76 1203.93,1348.32 1160.69,1355.45 1185.87,1367.33 1167.02,1385.23 174,1389 374,1389 574,1389 774,1389 974,1389 1063,1394.12 1213.49,1421.12 1164,1458 79,1478.41 1290.2,1505.05 1213.49,1518.29 1085,1523 1303.97,1545.63 203,1577 80,1580 574,1589 774,1589 974,1589 1174,1589 357,1626 1303.97,1629.42 1287,1746 87,1748 549,1769 179,1771 699,1798.12 854,1798.12 1009,1798.12 1164,1798.12 345,1800 1302,1801.12
  other v2: 1285.9,1026.09 1296.57,1044.91 1297.14,1065.55 1277.84,1076.67 1300.51,1094.28 1281.39,1100.42 1302.74,1113.74 1264.74,1119.05 1284.85,1120.34 1301.68,1132.42 1263.95,1138.47 1245.22,1140.15 1283.76,1139.66 1299.16,1159.05 1235.93,1167.19 1237.19,1188.11 1257.19,1188.11 1309.95,1212.33 1292.64,1218.81 1326.53,1220.93 1310.54,1231.44 1293.44,1241.12 1326.64,1241.72 1310.15,1250.39 1291.67,1263.48 1326.64,1264.49 1309.97,1269.35 1239.76,1289.48 1258.92,1289.07 1239.6,1308.88 1258.42,1308.96 1272.83,1325.61 1249.3,1327.12 1291.32,1333.99 1272.53,1345.41 1291.32,1352.38 1248.69,1356.12 1271.52,1366.92 1291.32,1371.2 1291.32,1390.2 1271.42,1393.09 1291.32,1409.2 1291.32,1427.75 1294,1473.12
IS-: MP2.1 U1.7
  other v1: 1362,679.12 1671,679.12 1826,679.12 1981,679.12 2136,679.12 2291,679.12 2446,679.12 2601,679.12 1489,680 1385,702 1456,812 2599,841 1494,843 1694,843 1894,843 2094,843 2294,843 2494,843 1375,847 1364.96,886.12 1429,905 1502,938.12 1377.04,954.19 2594,998.84 1694,1043 1894,1043 2094,1043 2294,1043 2494,1043 1473.48,1055.84 1625,1072 1506.48,1083.09 1489.48,1105.09 1516.38,1111.47 1473.48,1126.09 1500.38,1132.47 1455.96,1145.56 1483.38,1151.43 1602,1168.12 1466.17,1173.41 1585,1187.12 1558,1196.12 1693,1241.12 1494,1243 1894,1243 2094,1243 1558,1287.12 1585,1294.12 1607,1306.12 1461.83,1308.51 1481.24,1326.09 1457.77,1338.63 1499.85,1344.69 1476.95,1358.26 1517.21,1365.69 1495.67,1378.46 1620,1392.12 1513.95,1397.4 1457.77,1424.87 1494,1443 1694,1443 1894,1443 2094,1443 2294,1443 2494,1443 2594,1478.41 1390.53,1501.26 1462,1526 1595,1528 1389.53,1544.97 1374.92,1603.73 2594,1638.27 1494,1643 1694,1643 1894,1643 2094,1643 2294,1643 2494,1643 1375,1726 2594,1798.12 1521,1800.12 1676,1800.12 1831,1800.12 1986,1800.12 2141,1800.12 2296,1800.12 2451,1800.12 1375,1803.12
  other v2: 1361.12,1021.44 1396.09,1028.51 1427.53,1028.51 1365.62,1040.63 1386.35,1055.84 1365.56,1060.84 1427.53,1061.96 1398.37,1074.44 1422.9,1081.36 1406.71,1093.75 1424.17,1102.14 1442.91,1104.02 1395.06,1142.12 1404.11,1158.92 1438.06,1171.53 1418.61,1172.26 1420.19,1191.04 1439.82,1190.8 1364.8,1212.69 1384.6,1215.13 1351.27,1225.18 1369.3,1230.77 1385.02,1240.51 1351.27,1245.08 1369.47,1250.41 1387.31,1261.93 1351.27,1264.98 1369.59,1269.34 1419.9,1291.44 1439.49,1291.28 1418.46,1311.51 1438.21,1310.95 1366.28,1323.25 1385.36,1323.25 1404.7,1324.05 1360.88,1341.52 1411.06,1345.18 1360.54,1361.53 1380.71,1362.02 1401.65,1365.06 1360.63,1381.39 1380.87,1384.02 1409.09,1397.64 1360.75,1400.99 1383.9,1407.09 1371,1424.12 1392.89,1433.18 1371.76,1443.2 1363.57,1460.5 1367.97,1480.53
NetD1_2: D1.2 R4.2 | length 165.3
  Top Layer w10: D1.2@2115,2060.34 2182.34,2060.34 2194,2072 R4.2@2194,2153.5
NetD2_2: D2.2 R7.2 | length 95.2
  Top Layer w10: D2.2@2330,2172.34 2335.35,2166.99 R7.2@2423,2166.99
NetU1_1: U1.1 U1.2 | length 23.6
  Top Layer w10: U1.1@1279.94,1186 U1.2@1303.57,1186
NetU1_8: U1.8 U1.9 | length 23.6
  Top Layer w10: U1.9@1374.43,1296.24 U1.8@1398.06,1296.24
